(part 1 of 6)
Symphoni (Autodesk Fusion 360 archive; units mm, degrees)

design "Symphoni" references "Symphoni", "Back Panel", "Laser Panel", "Bearing_Test", "Cherry MX Keycap"
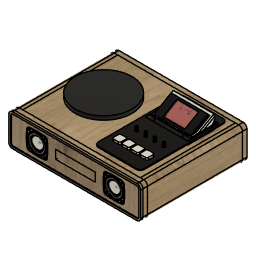
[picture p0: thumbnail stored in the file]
part number: Speaker 2 inch
parameter "Width" = 350
parameter "Height" = 85
parameter "Corner_Fillet" = 10
parameter "Length" = 216
parameter "M3_3D" = 3
parameter "M4_3D" = 4
parameter "M5_3D" = 5
parameter "Case_Holes" = 4 comment "The hole size of the screws holding the top plate to the sides"
sketch "Front_View" plane through (0, 0, 0) normal (0, 1, 0) x axis (1, 0, 0)
  line L1 (340, 0) -> (10, 0)
  line L2 (350, -75) -> (350, -10)
  line L3 (10, -85) -> (340, -85)
  line L4 (0, -10) -> (0, -75)
  line L5 (17, -78) -> (333, -78)
  line L6 (338, -70.8) -> (338, -17)
  line L7 (333, -12) -> (17, -12)
  line L8 (12, -17) -> (12, -71)
  line L9 (14.5, -73) -> (329.5, -73)
  line L10 (12, -14.5) -> (12, -70.5)
  line L11 (329.5, -12) -> (14.5, -12)
  line L12 (332, -70.5) -> (332, -14.5)
  line L13 (14, -73) -> (14.5, -73)
  line L14 (12, -12) -> (14.5, -12)
  line L15 (338, -12) -> (329.5, -12)
  line L16 (335.8, -73) -> (329.5, -73)
  line L17 (19.0012, -78) -> (19.0012, -85)
  line L18 (31.0012, -78) -> (19.0012, -78)
  line L19 (31.0012, -73) -> (31.0012, -78)
  line L20 (175, 0) -> (175, -85)
  line L21 (330.9988, -78) -> (330.9988, -85)
  line L22 (318.9988, -73) -> (318.9988, -78)
  arc A1 centre (10, -75) radius 10 clockwise from (10, -85) to (0, -75)
  arc A2 centre (340, -75) radius 10 clockwise from (350, -75) to (340, -85)
  arc A3 centre (340, -10) radius 10 clockwise from (340, 0) to (350, -10)
  arc A4 centre (10, -10) radius 10 clockwise from (0, -10) to (10, 0)
  arc A5 centre (17, -73) radius 5 clockwise from (17, -78) to (12, -73)
  arc A6 centre (17, -17) radius 5 clockwise from (12, -17) to (17, -12)
  arc A7 centre (333, -17) radius 5 clockwise from (333, -12) to (338, -17)
  arc A8 centre (333, -73) radius 5 clockwise from (338, -73) to (333, -78)
  arc A9 centre (14.5, -70.5) radius 2.5 clockwise from (14.5, -73) to (12, -70.5)
  arc A10 centre (329.5, -14.5) radius 2.5 clockwise from (329.5, -12) to (332, -14.5)
  arc A11 centre (329.5, -70.5) radius 2.5 clockwise from (332, -70.5) to (329.5, -73)
  arc A12 centre (14.5, -14.5) radius 2.5 clockwise from (12, -14.5) to (14.5, -12)
  arc A13 centre (14, -71) radius 2 clockwise from (14, -73) to (12, -71)
  arc A14 centre (335.8, -70.8) radius 2.2 clockwise from (338, -70.8) to (335.8, -73)
  point P1 (0, 0)
  point P2 (0, 0)
  point P4 (0, -85)
  point P3 (350, 0)
  point P41 (12, -12)
  point P42 (338, -12)
  point P43 (19.0012, -85)
  point P44 (19.0012, -78)
  point P45 (31.0012, -78)
  point P46 (31.0012, -73)
  point P47 (175, -85)
  point P48 (175, 0)
  point P49 (330.9988, -85)
  point P50 (330.9988, -78)
  point P51 (318.9988, -78)
  point P52 (318.9988, -73)
  point P18 (12, -73)
  point P27 (338, -73)
  horizontal L1
  vertical L2
  horizontal L3
  vertical L4
  coincident P1 P2
  coincident P4 L3
  coincident P4 L4
  tangent L3 A1
  tangent L4 A1
  tangent L2 A2
  tangent L3 A2
  equal A1 A2
  coincident P3 L1
  coincident P3 L2
  tangent L1 A3
  tangent L2 A3
  equal A1 A3
  coincident P2 L1
  coincident P2 L4
  tangent L1 A4
  tangent L4 A4
  equal A1 A4
  tangent L5 A5
  tangent L8 A5
  tangent L7 A6
  tangent L8 A6
  equal A5 A6
  tangent L6 A7
  tangent L7 A7
  equal A5 A7
  tangent L5 A8
  tangent L6 A8
  equal A5 A8
  tangent L9 A9
  tangent L10 A9
  tangent L11 A10
  tangent L12 A10
  equal A9 A10
  tangent L9 A11
  tangent L12 A11
  equal A9 A11
  tangent L10 A12
  tangent L11 A12
  equal A9 A12
  tangent A9 L13
  coincident L8 P41
  tangent A12 L14
  coincident L6 P42
  tangent A10 L15
  tangent A11 L16
  coincident L3 P43
  coincident L5 P44
  perpendicular L5 L17
  coincident L5 P45
  coincident L9 P46
  perpendicular L9 L19
  midpoint L3 P47
  midpoint L1 P48
  symmetric P43 L20 P49
  symmetric P44 L20 P50
  symmetric P45 L20 P51
  symmetric P46 L20 P52
  coincident L8 P18
  tangent L13 A13
  tangent L8 A13
  coincident L6 P27
  tangent L16 A14
  tangent L6 A14
  dimension "d3" distance P2 P3 = 350 (= "Width")
  dimension "d4" distance P2 P4 = 85 (= "Height")
  dimension "d5" radius A1 = 10 (= "Corner_Fillet")
  dimension "d8" radius A5 = 5 (= "Corner_Fillet / 2")
  dimension "d11" radius A9 = 2.5 (= "Corner_Fillet / 4")
  dimension "d12" distance P44 P45 = 12
  dimension "d13" radius A13 = 2
  dimension "d14" radius A14 = 2.2
extrude "Extrude1" new body sketch "Front_View" profile of L1 L2 L3 L4 A1 A2 A3 A4 L5 L7 L6 L8 A6 A7 L9 L11 L10 A12 L13 L15 L16 L17 L18 L19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 along normal blind 216 (= "Length")
sketch "Case_Hole" plane through (0, 0, 78) normal (0, 0, 1) x axis (-1, 0, 0)
  line L1 (-31.0012, 0) -> (-19.0012, 0)
  line L2 (-31.0012, -216) -> (-31.0012, 0)
  line L3 (-19.0012, -216) -> (-31.0012, -216)
  line L4 (-19.0012, 0) -> (-19.0012, -216)
  line L5 (-330.9988, 0) -> (-318.9988, 0)
  line L6 (-330.9988, -216) -> (-330.9988, 0)
  line L7 (-318.9988, -216) -> (-330.9988, -216)
  line L8 (-318.9988, 0) -> (-318.9988, -216)
  line L9 (-19.0012, -198) -> (-330.9988, -198)
  line L10 (-18.9896, -180) -> (-331.0104, -180)
  line L11 (-19.0012, -162) -> (-330.9988, -162)
  line L12 (-19.0012, -144) -> (-330.9988, -144)
  line L13 (-20, -126) -> (-330.9988, -126)
  line L14 (-333, -216) -> (-17, -216)
  line L15 (0, -18) -> (-330.9988, -18)
  line L16 (0.0025, -36) -> (-330.9988, -36)
  line L17 (0, -54) -> (-330.9988, -54)
  line L18 (-333, 0) -> (-17, 0)
  line L19 (-324.9988, -216) -> (-324.9988, 0)
  line L20 (-25.0012, -216) -> (-25.0012, 0)
  line L21 (-175, -216) -> (-175, 0)
  line L22 (-340, -108) -> (-19.0012, -108)
  circle C1 centre (-324.9988, -189) radius 2
  circle C2 centre (-324.9988, -27) radius 3.4926
  circle C3 centre (-25.0012, -188.5138) radius 2.9725
  circle C4 centre (-25.0012, -27.4042) radius 3.2246
  circle C5 centre (-25.0012, -189) radius 2
  circle C6 centre (-324.9988, -108) radius 2
  circle C7 centre (-25.0012, -108) radius 2
  point P10 (-330.9988, -198)
  point P11 (-19.0012, -198)
  point P14 (-330.9988, -162)
  point P15 (-19.0012, -162)
  point P16 (-330.9988, -144)
  point P17 (-19.0012, -144)
  point P18 (-330.9988, -126)
  point P22 (-330.9988, -18)
  point P24 (-330.9988, -36)
  point P26 (-330.9988, -54)
  point P30 (-324.9988, 0)
  point P31 (-324.9988, -216)
  point P32 (-25.0012, 0)
  point P33 (-25.0012, -216)
  point P34 (-324.9988, -189)
  point P35 (-324.9988, -27)
  point P36 (-25.0012, -188.5138)
  point P37 (-25.0012, -27.4042)
  point P38 (-175, 0)
  point P39 (-175, -216)
  point P40 (-25.0012, -27)
  point P42 (-19.0012, -108)
  point P44 (-324.9988, -108)
  coincident L6 P10
  coincident L4 P11
  perpendicular L4 L9
  coincident L6 P14
  coincident L4 P15
  perpendicular L4 L11
  coincident L6 P16
  coincident L4 P17
  perpendicular L4 L12
  coincident L6 P18
  perpendicular L2 L13
  horizontal L10
  coincident L6 P22
  perpendicular L6 L15
  coincident L6 P24
  coincident L6 P26
  perpendicular L2 L17
  horizontal L16
  midpoint L5 P30
  midpoint L7 P31
  midpoint L1 P32
  midpoint L3 P33
  coincident L19 P34
  coincident L19 P35
  coincident L20 P36
  coincident L20 P37
  midpoint L18 P38
  midpoint L14 P39
  symmetric C1 L21 C5
  symmetric P35 L21 P40
  midpoint L4 P42
  perpendicular L6 L22
  midpoint L19 P44
  symmetric L21 C6 C7
  dimension "d21" distance L9 L14 = 18
  dimension "d22" distance L9 L10 = 18
  dimension "d23" distance L15 L18 = 18
  dimension "d24" distance L15 L16 = 18
  dimension "d25" distance L16 L17 = 18
  dimension "d26" distance L10 L11 = 18
  dimension "d27" distance L11 L12 = 18
  dimension "d28" distance L12 L13 = 18
  dimension "d29" diameter C1 = 4 (= "Case_Holes")
  dimension "d30" distance L9 P34 = 9 (= "d22 / 2")
  dimension "d31" distance L15 P35 = 9 (= "d24 / 2")
  dimension "d34" diameter C6 = 4 (= "Case_Holes")
extrude "Extrude2" cut sketch "Case_Hole" profile of L17 C1 C2 C3 C4 C5 C6 C7 to an object
extrude "Extrude1" new body sketch "Front_View" profile of L3 L5 L9 L17 L18 L19 L21 L22 along normal blind 216 (= "Length")
extrude "Extrude2" cut sketch "Case_Hole" profile of L17 C1 C2 C3 C4 C5 C6 C7 along normal blind 4
sketch "Sketch3" plane through (0, 0, 85) normal (0, 0, 1) x axis (-1, 0, 0)
  line L1 (-330.9988, 0) -> (-19.0012, 0)
  line L2 (-330.9988, -216) -> (-330.9988, 0)
  line L3 (-19.0012, -216) -> (-330.9988, -216)
  line L4 (-19.0012, 0) -> (-19.0012, -216)
  line L5 (-315.3243, -196.9924) -> (-215.3243, -196.9924)
  line L6 (-315.3243, -25.6421) -> (-315.3243, -196.9924)
  line L7 (-215.3243, -25.6421) -> (-315.3243, -25.6421)
  line L8 (-215.3243, -196.9924) -> (-215.3243, -25.6421)
  circle C1 centre (-110, -108) radius 88.9
  point P6 (-110, -108)
  point P7 (-215.3243, -196.9924)
  point P8 (-315.3243, -196.9924)
  horizontal L5
  vertical L6
  horizontal L7
  vertical L8
  dimension "d40" diameter C1 = 177.8
  dimension "d41" distance L3 P6 = 108 (= "Length / 2")
  dimension "d42" distance P7 P8 = 100
sketch "Sketch1" plane through (0, 216, 0) normal (0, 1, 0) x axis (-1, 0, 0)
  line L1 (-330.9988, 78) -> (-330.9988, 85)
  line L2 (-318.9988, 78) -> (-330.9988, 78)
  line L3 (-318.9988, 73) -> (-318.9988, 78)
  line L4 (-31.0012, 73) -> (-318.9988, 73)
  line L5 (-31.0012, 78) -> (-31.0012, 73)
  line L6 (-19.0012, 78) -> (-31.0012, 78)
  line L7 (-19.0012, 85) -> (-19.0012, 78)
  line L8 (-330.9988, 85) -> (-19.0012, 85)
  line L9 (-318.9988, 73) -> (-335.8, 73)
  line L10 (-318.9988, 78) -> (-318.9988, 73)
  line L11 (-330.9988, 78) -> (-318.9988, 78)
  line L12 (-330.9988, 85) -> (-330.9988, 78)
  line L13 (-340, 85) -> (-330.9988, 85)
  line L14 (-350, 10) -> (-350, 75)
  line L15 (-10, 0) -> (-340, 0)
  line L16 (0, 75) -> (0, 10)
  line L17 (-19.0012, 85) -> (-10, 85)
  line L18 (-19.0012, 78) -> (-19.0012, 85)
  line L19 (-31.0012, 78) -> (-19.0012, 78)
  line L20 (-31.0012, 73) -> (-31.0012, 78)
  line L21 (-14, 73) -> (-31.0012, 73)
  line L22 (-12, 17) -> (-12, 71)
  line L23 (-333, 12) -> (-17, 12)
  line L24 (-338, 70.8) -> (-338, 17)
  line L25 (-175, 0) -> (-175, 85)
  line L26 (-350, 42.5) -> (0, 42.5)
  line L27 (-217.5, 25) -> (-132.5, 25)
  line L28 (-222.5, 55) -> (-222.5, 30)
  line L29 (-132.5, 60) -> (-217.5, 60)
  line L30 (-127.5, 30) -> (-127.5, 55)
  line L31 (-222.5, 60) -> (-127.5, 25)
  line L32 (-127.5, 60) -> (-222.5, 25)
  arc A1 centre (-340, 75) radius 10 clockwise from (-350, 75) to (-340, 85)
  arc A2 centre (-340, 10) radius 10 clockwise from (-340, 0) to (-350, 10)
  arc A3 centre (-10, 10) radius 10 clockwise from (0, 10) to (-10, 0)
  arc A4 centre (-10, 75) radius 10 clockwise from (-10, 85) to (0, 75)
  arc A5 centre (-14, 71) radius 2 clockwise from (-14, 73) to (-12, 71)
  arc A6 centre (-17, 17) radius 5 clockwise from (-12, 17) to (-17, 12)
  arc A7 centre (-333, 17) radius 5 clockwise from (-333, 12) to (-338, 17)
  arc A8 centre (-335.8, 70.8) radius 2.2 clockwise from (-338, 70.8) to (-335.8, 73)
  arc A9 centre (-217.5, 55) radius 5 clockwise from (-222.5, 55) to (-217.5, 60)
  arc A10 centre (-132.5, 55) radius 5 clockwise from (-132.5, 60) to (-127.5, 55)
  arc A11 centre (-132.5, 30) radius 5 clockwise from (-127.5, 30) to (-132.5, 25)
  arc A12 centre (-217.5, 30) radius 5 clockwise from (-217.5, 25) to (-222.5, 30)
  point P42 (-175, 85)
  point P43 (-175, 0)
  point P44 (0, 42.5)
  point P45 (-350, 42.5)
  point P50 (-175, 42.5)
  point P48 (-222.5, 60)
  point P49 (-127.5, 60)
  point P46 (-127.5, 25)
  point P47 (-222.5, 25)
  midpoint L8 P42
  midpoint L15 P43
  midpoint L16 P44
  midpoint L14 P45
  horizontal L27
  perpendicular L27 L28
  parallel L27 L29
  parallel L28 L30
  coincident L31 P50
  coincident L32 P50
  midpoint L25 P50
  coincident P48 L29
  coincident P48 L28
  tangent L29 A9
  tangent L28 A9
  coincident P49 L29
  coincident P49 L30
  tangent L29 A10
  tangent L30 A10
  equal A9 A10
  coincident P46 L27
  coincident P46 L30
  tangent L27 A11
  tangent L30 A11
  equal A9 A11
  coincident P47 L28
  coincident P47 L27
  tangent L28 A12
  tangent L27 A12
  equal A9 A12
  dimension "d45" distance P48 P49 = 95
  dimension "d46" distance P47 P48 = 35
  dimension "d47" radius A9 = 5
extrude "Extrude1" new body sketch "Sketch1" profile of L1 L2 L3 L4 L5 L6 L7 L8 L9 L10 L11 L12 L13 A1 L14 A2 L15 A3 L16 A4 L17 L18 L19 L20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 along normal blind 12
extrude "Extrude3" cut sketch "Sketch3" profile of L5 L6 L7 L8 against normal blind 25
component_insert "Component Insert2"
component_from_bodies "Body->Comp1"
sketch "Sketch2" plane through (0, 216, 0) normal (0, 1, 0) x axis (-1, 0, 0)
  line L1 (-318.9988, 73) -> (-335.8, 73)
  line L2 (-318.9988, 78) -> (-318.9988, 73)
  line L3 (-330.9988, 78) -> (-318.9988, 78)
  line L4 (-330.9988, 85) -> (-330.9988, 78)
  line L5 (-340, 85) -> (-330.9988, 85)
  line L6 (-350, 10) -> (-350, 75)
  line L7 (-10, 0) -> (-340, 0)
  line L8 (0, 75) -> (0, 10)
  line L9 (-19.0012, 85) -> (-10, 85)
  line L10 (-19.0012, 78) -> (-19.0012, 85)
  line L11 (-31.0012, 78) -> (-19.0012, 78)
  line L12 (-31.0012, 73) -> (-31.0012, 78)
  line L13 (-14, 73) -> (-31.0012, 73)
  line L14 (-12, 17) -> (-12, 71)
  line L15 (-333, 12) -> (-17, 12)
  line L16 (-338, 70.8) -> (-338, 17)
  arc A1 centre (-340, 75) radius 10 clockwise from (-350, 75) to (-340, 85)
  arc A2 centre (-340, 10) radius 10 clockwise from (-340, 0) to (-350, 10)
  arc A3 centre (-10, 10) radius 10 clockwise from (0, 10) to (-10, 0)
  arc A4 centre (-10, 75) radius 10 clockwise from (-10, 85) to (0, 75)
  arc A5 centre (-14, 71) radius 2 clockwise from (-14, 73) to (-12, 71)
  arc A6 centre (-17, 17) radius 5 clockwise from (-12, 17) to (-17, 12)
  arc A7 centre (-333, 17) radius 5 clockwise from (-333, 12) to (-338, 17)
  arc A8 centre (-335.8, 70.8) radius 2.2 clockwise from (-338, 70.8) to (-335.8, 73)
  circle C1 centre (-340, 78) radius 2
  circle C2 centre (-340, 6.9916) radius 2
  circle C3 centre (-175, 6.9916) radius 2
  circle C4 centre (-175, 79) radius 2
  circle C5 centre (-9.989, 78) radius 2
  circle C6 centre (-10, 7.35) radius 2
  dimension "d52" diameter C1 = 4 (= "Case_Holes")
  dimension "d53" diameter C2 = 4 (= "Case_Holes")
  dimension "d54" diameter C3 = 4 (= "Case_Holes")
  dimension "d55" diameter C4 = 4 (= "Case_Holes")
  dimension "d56" diameter C5 = 4 (= "Case_Holes")
  dimension "d57" diameter C6 = 4 (= "Case_Holes")
extrude "Extrude4" cut sketch "Sketch2" profile of C1 C2 C3 C4 C5 C6 against normal blind 5 and along normal blind 15
sketch "Sketch3" plane through (0, 0, 85) normal (0, 0, 1) x axis (-1, 0, 0)
  line L1 (-315.3243, -25.6421) -> (-315.3243, -196.9924)
  line L2 (-215.3243, -25.6421) -> (-315.3243, -25.6421)
  line L3 (-215.3243, -196.9924) -> (-215.3243, -25.6421)
  line L4 (-315.3243, -196.9924) -> (-215.3243, -196.9924)
  line L5 (-330.9988, 0) -> (-19.0012, 0)
  line L6 (-330.9988, -216) -> (-330.9988, 0)
  line L7 (-19.0012, -216) -> (-330.9988, -216)
  line L8 (-19.0012, 0) -> (-19.0012, -216)
  line L9 (-214.0809, -145.3115) -> (-311.7625, -145.3115)
  line L10 (-214.0809, -198.1908) -> (-214.0809, -145.3115)
  line L11 (-311.7625, -198.1908) -> (-214.0809, -198.1908)
  line L12 (-311.7625, -145.3115) -> (-311.7625, -198.1908)
  line L13 (-316.7625, -140.3115) -> (-209.0809, -140.3115)
  line L14 (-316.7625, -203.1908) -> (-316.7625, -140.3115)
  line L15 (-209.0809, -203.1908) -> (-316.7625, -203.1908)
  line L16 (-209.0809, -140.3115) -> (-209.0809, -203.1908)
  line L17 (-318.7625, -138.3115) -> (-207.0809, -138.3115)
  line L18 (-318.7625, -205.1908) -> (-318.7625, -138.3115)
  line L19 (-207.0809, -205.1908) -> (-318.7625, -205.1908)
  line L20 (-207.0809, -138.3115) -> (-207.0809, -205.1908)
  dimension "d75" = 2
extrude "Extrude6" cut sketch "Sketch3" profile of L1 L3 L4 L9 L10 L11 L12 L13 L14 L15 L16 L18 L17 L19 L20 against normal blind 20
sketch "Sketch11" plane through (0, 227.5, 0) normal (0, -1, 0) x axis (1, 0, 0)
  line L1 (227.4494, 58.544) -> (227.4494, 28.544)
  line L2 (127.4494, 63.544) -> (222.4494, 63.544)
  line L3 (122.4494, 28.544) -> (122.4494, 58.544)
  line L4 (222.4494, 23.544) -> (127.4494, 23.544)
  line L5 (193.2946, 52.6567) -> (193.2946, 61.6567)
  line L6 (186.2946, 52.6567) -> (193.2946, 52.6567)
  line L7 (186.2946, 61.6567) -> (186.2946, 52.6567)
  line L8 (193.2946, 61.6567) -> (186.2946, 61.6567)
  line L9 (186.291, 51.1467) -> (186.291, 46.6467)
  line L10 (193.291, 51.1467) -> (186.291, 51.1467)
  line L11 (193.291, 46.6467) -> (193.291, 51.1467)
  line L12 (186.291, 46.6467) -> (193.291, 46.6467)
  line L13 (137.5637, 51.1467) -> (137.5637, 45.1467)
  line L14 (144, 51.1467) -> (137.5637, 51.1467)
  line L15 (144, 45.1467) -> (144, 51.1467)
  line L16 (137.5637, 45.1467) -> (144, 45.1467)
  line L17 (159.4932, 39.0374) -> (159.4932, 49.0374)
  line L18 (152.4932, 39.0374) -> (159.4932, 39.0374)
  line L19 (152.4932, 49.0374) -> (152.4932, 39.0374)
  line L20 (159.4932, 49.0374) -> (152.4932, 49.0374)
  line L21 (194.5687, 39.0374) -> (194.5687, 45.5374)
  line L22 (187.5687, 39.0374) -> (194.5687, 39.0374)
  line L23 (187.5687, 45.5374) -> (187.5687, 39.0374)
  line L24 (194.5687, 45.5374) -> (187.5687, 45.5374)
  line L25 (170.35, 37.6424) -> (170.35, 27.0424)
  line L26 (179.65, 37.6424) -> (170.35, 37.6424)
  line L27 (179.65, 27.0424) -> (179.65, 37.6424)
  line L28 (171.05, 26.3424) -> (178.95, 26.3424)
  line L29 (127.5, 30) -> (127.5, 55)
  line L30 (132.5, 60) -> (217.5, 60)
  line L31 (217.5, 25) -> (132.5, 25)
  line L32 (222.5, 55) -> (222.5, 30)
  line L33 (129.5, 30) -> (129.5, 55)
  line L34 (217.5, 27) -> (132.5, 27)
  line L35 (220.5, 55) -> (220.5, 30)
  line L36 (132.5, 58) -> (217.5, 58)
  line L37 (182, 27) -> (167, 27)
  line L38 (182, 25) -> (182, 27)
  line L39 (167, 25) -> (182, 25)
  line L40 (167, 27) -> (167, 25)
  arc A1 centre (222.4494, 28.544) radius 5 clockwise from (227.4494, 28.544) to (222.4494, 23.544)
  arc A2 centre (222.4494, 58.544) radius 5 clockwise from (222.4494, 63.544) to (227.4494, 58.544)
  arc A3 centre (127.4494, 58.544) radius 5 clockwise from (122.4494, 58.544) to (127.4494, 63.544)
  arc A4 centre (127.4494, 28.544) radius 5 clockwise from (127.4494, 23.544) to (122.4494, 28.544)
  circle C1 centre (175, 46.2153) radius 2.7
  arc A5 centre (178.95, 27.0424) radius 0.7 clockwise from (179.65, 27.0424) to (178.95, 26.3424)
  arc A6 centre (171.05, 27.0424) radius 0.7 clockwise from (171.05, 26.3424) to (170.35, 27.0424)
  arc A7 centre (132.5, 55) radius 5 clockwise from (127.5, 55) to (132.5, 60)
  arc A8 centre (132.5, 30) radius 5 clockwise from (132.5, 25) to (127.5, 30)
  arc A9 centre (217.5, 30) radius 5 clockwise from (222.5, 30) to (217.5, 25)
  arc A10 centre (217.5, 55) radius 5 clockwise from (217.5, 60) to (222.5, 55)
  arc A11 centre (132.5, 30) radius 3 clockwise from (132.5, 27) to (129.5, 30)
  arc A12 centre (217.5, 30) radius 3 clockwise from (220.5, 30) to (217.5, 27)
  arc A13 centre (217.5, 55) radius 3 clockwise from (217.5, 58) to (220.5, 55)
  arc A14 centre (132.5, 55) radius 3 clockwise from (129.5, 55) to (132.5, 58)
  point P69 (182, 25)
  point P67 (167, 27)
  horizontal L37
  vertical L38
  horizontal L39
  vertical L40
  coincident L31 P69
  coincident L34 P67
  dimension "d141" = -2
offset_faces "OffsetFaces1" distance 36
position "Position9"
sketch "Sketch12" plane through (0, 0, 88.7) normal (0, 0, 1) x axis (-1, 0, 0)
  line L1 (-313.7625, -161.3779) -> (-313.7625, -215.1735)
  line L2 (-206.1516, -161.3779) -> (-313.7625, -161.3779)
  line L3 (-206.1516, -186.4735) -> (-206.1516, -161.3779)
  line L4 (-206.1515, -186.4735) -> (-206.1516, -186.4735)
  line L5 (-206.1515, -188.1735) -> (-206.1515, -186.4735)
  line L6 (-206.1516, -188.1735) -> (-206.1515, -188.1735)
  line L7 (-206.1516, -213.4735) -> (-206.1516, -188.1735)
  line L8 (-206.1515, -213.4735) -> (-206.1516, -213.4735)
  line L9 (-206.1515, -215.1735) -> (-206.1515, -213.4735)
  line L10 (-313.7625, -215.1735) -> (-206.1515, -215.1735)
  line L11 (-313.7625, -125.5942) -> (-313.7625, -152.5942)
  line L12 (-206.1516, -125.5942) -> (-313.7625, -125.5942)
  line L13 (-206.1516, -152.5942) -> (-206.1516, -125.5942)
  line L14 (-313.7625, -152.5942) -> (-206.1516, -152.5942)
  line L15 (-209.081, -225) -> (-311.081, -225)
  line L16 (-199.081, -5) -> (-199.081, -215)
  line L17 (-311.081, 5) -> (-209.081, 5)
  line L18 (-321.081, -215) -> (-321.081, -5)
  arc A1 centre (-311.081, -215) radius 10 clockwise from (-311.081, -225) to (-321.081, -215)
  arc A2 centre (-209.081, -215) radius 10 clockwise from (-199.081, -215) to (-209.081, -225)
  arc A3 centre (-209.081, -5) radius 10 clockwise from (-209.081, 5) to (-199.081, -5)
  arc A4 centre (-311.081, -5) radius 10 clockwise from (-321.081, -5) to (-311.081, 5)
sketch "Sketch13" plane through (0, 0, 0) normal (0, -1, 0) x axis (1, 0, 0)
  line L1 (330.9988, 85) -> (330.9988, 78)
  line L2 (19.0012, 85) -> (330.9988, 85)
  line L3 (19.0012, 78) -> (19.0012, 85)
  line L4 (31.0012, 78) -> (19.0012, 78)
  line L5 (31.0012, 73) -> (31.0012, 78)
  line L6 (318.9988, 73) -> (31.0012, 73)
  line L7 (318.9988, 78) -> (318.9988, 73)
  line L8 (330.9988, 78) -> (318.9988, 78)
  line L9 (335.8, 73) -> (318.9988, 73)
  line L10 (338, 17) -> (338, 70.8)
  line L11 (17, 12) -> (333, 12)
  line L12 (12, 71) -> (12, 17)
  line L13 (31.0012, 73) -> (14, 73)
  line L14 (31.0012, 78) -> (31.0012, 73)
  line L15 (19.0012, 78) -> (31.0012, 78)
  line L16 (19.0012, 85) -> (19.0012, 78)
  line L17 (10, 85) -> (19.0012, 85)
  line L18 (0, 10) -> (0, 75)
  line L19 (340, 0) -> (10, 0)
  line L20 (350, 75) -> (350, 10)
  line L21 (330.9988, 85) -> (340, 85)
  line L22 (330.9988, 78) -> (330.9988, 85)
  line L23 (318.9988, 78) -> (330.9988, 78)
  line L24 (318.9988, 73) -> (318.9988, 78)
  arc A1 centre (335.8, 70.8) radius 2.2 clockwise from (335.8, 73) to (338, 70.8)
  arc A2 centre (333, 17) radius 5 clockwise from (338, 17) to (333, 12)
  arc A3 centre (17, 17) radius 5 clockwise from (17, 12) to (12, 17)
  arc A4 centre (14, 71) radius 2 clockwise from (12, 71) to (14, 73)
  arc A5 centre (10, 75) radius 10 clockwise from (0, 75) to (10, 85)
  arc A6 centre (10, 10) radius 10 clockwise from (10, 0) to (0, 10)
  arc A7 centre (340, 10) radius 10 clockwise from (350, 10) to (340, 0)
  arc A8 centre (340, 75) radius 10 clockwise from (340, 85) to (350, 75)
place_component sketch "Sketch13"
extrude "Extrude1" new body sketch "Sketch13" along normal blind 12
component_insert "Component Insert7"
position "Position10"
sketch "Sketch14" plane through (0, 0, 0) normal (0, -1, 0) x axis (1, 0, 0)
  line L1 (335.8, 73) -> (318.9988, 73)
  line L2 (338, 17) -> (338, 70.8)
  line L3 (17, 12) -> (333, 12)
  line L4 (12, 71) -> (12, 17)
  line L5 (31.0012, 73) -> (14, 73)
  line L6 (31.0012, 78) -> (31.0012, 73)
  line L7 (19.0012, 78) -> (31.0012, 78)
  line L8 (19.0012, 85) -> (19.0012, 78)
  line L9 (10, 85) -> (19.0012, 85)
  line L10 (0, 10) -> (0, 75)
  line L11 (340, 0) -> (10, 0)
  line L12 (350, 75) -> (350, 10)
  line L13 (330.9988, 85) -> (340, 85)
  line L14 (330.9988, 78) -> (330.9988, 85)
  line L15 (318.9988, 78) -> (330.9988, 78)
  line L16 (318.9988, 73) -> (318.9988, 78)
  line L17 (330.9988, 85) -> (19.0012, 85)
  line L18 (31.0012, 73) -> (318.9988, 73)
  arc A1 centre (335.8, 70.8) radius 2.2 clockwise from (335.8, 73) to (338, 70.8)
  arc A2 centre (333, 17) radius 5 clockwise from (338, 17) to (333, 12)
  arc A3 centre (17, 17) radius 5 clockwise from (17, 12) to (12, 17)
  arc A4 centre (14, 71) radius 2 clockwise from (12, 71) to (14, 73)
  arc A5 centre (10, 75) radius 10 clockwise from (0, 75) to (10, 85)
  arc A6 centre (10, 10) radius 10 clockwise from (10, 0) to (0, 10)
  arc A7 centre (340, 10) radius 10 clockwise from (350, 10) to (340, 0)
  arc A8 centre (340, 75) radius 10 clockwise from (340, 85) to (350, 75)
  point P18 (19.0012, 85)
  point P34 (19.0012, 85)
  point P31 (330.9988, 85)
  point P35 (330.9988, 85)
  point P2 (318.9988, 73)
  point P36 (318.9988, 73)
  point P15 (31.0012, 73)
  point P37 (31.0012, 73)
  coincident P18 P34
  coincident P31 P35
  coincident P2 P36
  coincident P15 P37
extrude "Extrude6" new body sketch "Sketch14" along normal blind 18 bodies "Front"
sketch "Sketch15" plane through (0, -18, 0) normal (0, -1, 0) x axis (1, 0, 0)
  line L1 (0, 10) -> (0, 75)
  line L2 (340, 0) -> (10, 0)
  line L3 (350, 75) -> (350, 10)
  line L4 (10, 85) -> (340, 85)
  line L5 (10, 80) -> (340, 80)
  line L6 (5, 10) -> (5, 75)
  line L7 (340, 5) -> (10, 5)
  line L8 (345, 75) -> (345, 10)
  arc A1 centre (10, 75) radius 10 clockwise from (0, 75) to (10, 85)
  arc A2 centre (10, 10) radius 10 clockwise from (10, 0) to (0, 10)
  arc A3 centre (340, 10) radius 10 clockwise from (350, 10) to (340, 0)
  arc A4 centre (340, 75) radius 10 clockwise from (340, 85) to (350, 75)
  arc A5 centre (10, 75) radius 5 clockwise from (5, 75) to (10, 80)
  arc A6 centre (10, 10) radius 5 clockwise from (10, 5) to (5, 10)
  arc A7 centre (340, 10) radius 5 clockwise from (345, 10) to (340, 5)
  arc A8 centre (340, 75) radius 5 clockwise from (340, 80) to (345, 75)
  dimension "d148" = -5
extrude "Extrude7" cut sketch "Sketch15" profile of A8 L6 A6 L8 L5 L7 A5 A7 against normal blind 2
base_feature "Base Feature1"
position "Position11"
sketch "Sketch16" plane through (0, -16, 0) normal (0, -1, 0) x axis (1, 0, 0)
  line L1 (10, 80) -> (340, 80)
  line L2 (5, 10) -> (5, 75)
  line L3 (340, 5) -> (10, 5)
  line L4 (345, 75) -> (345, 10)
  line L5 (175, 0) -> (175, 85)
  line L6 (5, 42.5) -> (345, 42.5)
  line L7 (44.9825, 14.5) -> (100.9825, 14.5)
  line L8 (44.9825, 70.5) -> (44.9825, 14.5)
  line L9 (100.9825, 70.5) -> (44.9825, 70.5)
  line L10 (100.9825, 14.5) -> (100.9825, 70.5)
  line L11 (44.9825, 70.5) -> (100.9825, 14.5)
  line L12 (100.9825, 70.5) -> (44.9825, 14.5)
  arc A1 centre (340, 75) radius 5 clockwise from (340, 80) to (345, 75)
  arc A2 centre (10, 75) radius 5 clockwise from (5, 75) to (10, 80)
  arc A3 centre (10, 10) radius 5 clockwise from (10, 5) to (5, 10)
  arc A4 centre (340, 10) radius 5 clockwise from (345, 10) to (340, 5)
  circle C1 centre (277.0175, 42.5) radius 27.5
  point P16 (345, 42.5)
  point P17 (5, 42.5)
  point P18 (277.0175, 42.5)
  point P23 (72.9825, 42.5)
  point P21 (44.9825, 70.5)
  point P22 (100.9825, 70.5)
  point P20 (44.9825, 14.5)
  perpendicular L1 L5
  midpoint L4 P16
  midpoint L2 P17
  coincident L6 P18
  horizontal L7
  perpendicular L7 L8
  parallel L7 L9
  parallel L8 L10
  coincident L11 P23
  coincident L12 P23
  dimension "d152" diameter C1 = 55
  dimension "d153" distance P21 P22 = 56
  dimension "d154" distance P20 P21 = 56
joint "Assemble3" GlobalReorient0 0 GlobalReorient1 0 alignAngle 90 alignOffsetX 0 alignOffsetY 0 alignOffsetZ -4 GlobalReorient0 0 GlobalReorient1 0 GlobalReorient0 0 GlobalReorient1 0 GlobalReorient0 0 GlobalReorient1 0 GlobalReorient0 0 GlobalReorient1 0 GlobalReorient0 0 GlobalReorient1 0 GlobalReorient0 0 GlobalReorient1 0 GlobalReorient0 0 GlobalReorient1 0
sketch "Sketch17" plane through (145.965, -16.0943, 85) normal (0, -1, 0) x axis (-1, 0, 0)
  line L1 (54.11, 64.2009) -> (53.4029, 64.908)
  line L2 (50.5745, 62.0796) -> (51.2816, 61.3725)
  line L3 (51.2816, 23.6275) -> (50.5745, 22.9204)
  line L4 (53.4029, 20.092) -> (54.11, 20.7991)
  line L5 (91.855, 20.7991) -> (92.5621, 20.092)
  line L6 (95.3905, 22.9204) -> (94.6834, 23.6275)
  line L7 (94.6834, 61.3725) -> (95.3905, 62.0796)
  line L8 (92.5621, 64.908) -> (91.855, 64.2009)
  line L9 (135.965, 5) -> (-194.035, 5)
  line L10 (140.965, 75) -> (140.965, 10)
  line L11 (-194.035, 80) -> (135.965, 80)
  line L12 (-199.035, 10) -> (-199.035, 75)
  line L13 (140.965, 42.5) -> (-199.035, 42.5)
  line L14 (-29.035, 80) -> (-29.035, 5)
  line L15 (23.5429, 53.9909) -> (-81.6129, 53.9909)
  line L16 (23.5429, 31.0091) -> (23.5429, 53.9909)
  line L17 (-81.6129, 31.0091) -> (23.5429, 31.0091)
  line L18 (-81.6129, 53.9909) -> (-81.6129, 31.0091)
  line L19 (23.5429, 31.0091) -> (-81.6129, 53.9909)
  line L20 (-81.6129, 31.0091) -> (23.5429, 53.9909)
  line L21 (-72.6746, 31.0091) -> (-81.6129, 31.0091)
  line L22 (-72.6746, 53.9909) -> (-72.6746, 31.0091)
  line L23 (-81.6129, 53.9909) -> (-72.6746, 53.9909)
  line L24 (-81.6129, 31.0091) -> (-81.6129, 53.9909)
  arc A1 centre (51.9887, 21.5062) radius 4 clockwise from (51.4177, 17.5472) to (48.0296, 20.9352)
  arc A2 centre (72.9825, 167.0625) radius 151.0625 clockwise from (94.5473, 17.5472) to (51.4177, 17.5472)
  arc A3 centre (93.9763, 21.5062) radius 4 clockwise from (97.9353, 20.9352) to (94.5473, 17.5472)
  arc A4 centre (-51.58, 42.5) radius 151.0625 clockwise from (97.9353, 64.0648) to (97.9353, 20.9352)
  arc A5 centre (93.9763, 63.4938) radius 4 clockwise from (94.5473, 67.4528) to (97.9353, 64.0648)
  arc A6 centre (72.9825, -82.0625) radius 151.0625 clockwise from (51.4177, 67.4528) to (94.5473, 67.4528)
  arc A7 centre (51.9887, 63.4938) radius 4 clockwise from (48.0296, 64.0648) to (51.4177, 67.4528)
  arc A8 centre (197.545, 42.5) radius 151.0625 clockwise from (48.0296, 20.9352) to (48.0296, 64.0648)
  circle C1 centre (72.9825, 42.5) radius 25.7849
  arc A9 centre (51.9887, 63.4938) radius 2 clockwise from (50.5745, 62.0796) to (53.4029, 64.908)
  arc A10 centre (52.6958, 62.7867) radius 2 clockwise from (54.11, 64.2009) to (51.2816, 61.3725)
  arc A11 centre (51.9887, 21.5062) radius 2 clockwise from (53.4029, 20.092) to (50.5745, 22.9204)
  arc A12 centre (52.6958, 22.2133) radius 2 clockwise from (51.2816, 23.6275) to (54.11, 20.7991)
  arc A13 centre (93.9763, 21.5062) radius 2 clockwise from (95.3905, 22.9204) to (92.5621, 20.092)
  arc A14 centre (93.2692, 22.2133) radius 2 clockwise from (91.855, 20.7991) to (94.6834, 23.6275)
  arc A15 centre (93.9763, 63.4938) radius 2 clockwise from (92.5621, 64.908) to (95.3905, 62.0796)
  arc A16 centre (93.2692, 62.7867) radius 2 clockwise from (94.6834, 61.3725) to (91.855, 64.2009)
  arc A17 centre (197.545, 42.5) radius 151.0625 clockwise from (48.0296, 20.9352) to (48.0296, 64.0648)
  circle C2 centre (72.9825, 42.5) radius 25.7849
  arc A18 centre (72.9825, -82.0625) radius 151.0625 clockwise from (51.4177, 67.4528) to (94.5473, 67.4528)
  arc A19 centre (51.9887, 63.4938) radius 4 clockwise from (48.0296, 64.0648) to (51.4177, 67.4528)
  arc A20 centre (197.545, 42.5) radius 151.0625 clockwise from (48.0296, 20.9352) to (48.0296, 64.0648)
  arc A21 centre (51.9887, 21.5062) radius 4 clockwise from (51.4177, 17.5472) to (48.0296, 20.9352)
  arc A22 centre (72.9825, 167.0625) radius 151.0625 clockwise from (94.5473, 17.5472) to (51.4177, 17.5472)
  arc A23 centre (93.9763, 21.5062) radius 4 clockwise from (97.9353, 20.9352) to (94.5473, 17.5472)
  arc A24 centre (-51.58, 42.5) radius 151.0625 clockwise from (97.9353, 64.0648) to (97.9353, 20.9352)
  arc A25 centre (93.9763, 63.4938) radius 4 clockwise from (94.5473, 67.4528) to (97.9353, 64.0648)
  arc A26 centre (197.545, 42.5) radius 153.0625 clockwise from (46.0501, 20.6497) to (46.0501, 64.3503)
  arc A27 centre (51.9887, 21.5062) radius 6 clockwise from (51.1322, 15.5676) to (46.0501, 20.6497)
  arc A28 centre (72.9825, 167.0625) radius 153.0625 clockwise from (94.8328, 15.5676) to (51.1322, 15.5676)
  arc A29 centre (93.9763, 21.5062) radius 6 clockwise from (99.9148, 20.6497) to (94.8328, 15.5676)
  arc A30 centre (-51.58, 42.5) radius 153.0625 clockwise from (99.9148, 64.3503) to (99.9148, 20.6497)
  arc A31 centre (93.9763, 63.4938) radius 6 clockwise from (94.8328, 69.4324) to (99.9148, 64.3503)
  arc A32 centre (72.9825, -82.0625) radius 153.0625 clockwise from (51.1322, 69.4324) to (94.8328, 69.4324)
  arc A33 centre (51.9887, 63.4938) radius 6 clockwise from (46.0501, 64.3503) to (51.1322, 69.4324)
  arc A34 centre (-194.035, 10) radius 5 clockwise from (-194.035, 5) to (-199.035, 10)
  arc A35 centre (135.965, 10) radius 5 clockwise from (140.965, 10) to (135.965, 5)
  arc A36 centre (135.965, 75) radius 5 clockwise from (135.965, 80) to (140.965, 75)
  arc A37 centre (-194.035, 75) radius 5 clockwise from (-199.035, 75) to (-194.035, 80)
  point P95 (-199.035, 42.5)
  point P96 (140.965, 42.5)
  point P97 (-29.035, 5)
  point P98 (-29.035, 80)
  point P103 (-29.035, 42.5)
  point P105 (-72.6746, 53.9909)
  midpoint L12 P95
  midpoint L10 P96
  midpoint L9 P97
  midpoint L11 P98
  horizontal L15
  perpendicular L15 L16
  parallel L15 L17
  parallel L16 L18
  coincident L19 P103
  coincident L20 P103
  midpoint L14 P103
  horizontal L21
  vertical L22
  horizontal L23
  vertical L24
  coincident L15 P105
  dimension "d180" = 2
extrude "Extrude11" cut sketch "Sketch17" profile of C1 C2 to an object
extrude "Extrude12" cut sketch "Sketch17" profile of A1 A2 A3 A4 A5 A6 A7 A8 C1 A9 L1 A10 L2 A11 L3 A12 L4 A13 L5 A14 L6 A15 L7 A16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 against normal blind 7
work_plane "WorkPlane12"
mirror "Mirror1" mirrorStitchTolerance 0.1
extrude "Extrude13" cut sketch "Sketch17" profile of L15 L17 L18 L21 L22 L23 L24 against normal blind 30
extrude "Extrude2" cut sketch "Sketch17" profile of L15 L16 L17 L22 against normal blind 6.5
sketch "Sketch19" plane through (0, -18, 0) normal (0, -1, 0) x axis (1, 0, 0)
  line L1 (340, 80) -> (10, 80)
  line L2 (345, 10) -> (345, 75)
  line L3 (10, 5) -> (340, 5)
  line L4 (5, 75) -> (5, 10)
  line L5 (0, 10) -> (0, 75)
  line L6 (340, 0) -> (10, 0)
  line L7 (350, 75) -> (350, 10)
  line L8 (10, 85) -> (340, 85)
  line L9 (10, 80) -> (340, 80)
  line L10 (5, 10) -> (5, 75)
  line L11 (340, 5) -> (10, 5)
  line L12 (345, 75) -> (345, 10)
  line L13 (122.4221, 53.9909) -> (218.6396, 53.9909)
  line L14 (122.4221, 31.0091) -> (122.4221, 53.9909)
  line L15 (218.6396, 31.0091) -> (122.4221, 31.0091)
  line L16 (218.6396, 53.9909) -> (218.6396, 31.0091)
  line L17 (122.4221, 31.0091) -> (227.5779, 31.0091)
  line L18 (122.4221, 53.9909) -> (122.4221, 31.0091)
  line L19 (227.5779, 53.9909) -> (122.4221, 53.9909)
  line L20 (227.5779, 31.0091) -> (227.5779, 53.9909)
  arc A1 centre (340, 75) radius 5 clockwise from (340, 80) to (345, 75)
  arc A2 centre (340, 10) radius 5 clockwise from (345, 10) to (340, 5)
  arc A3 centre (10, 10) radius 5 clockwise from (10, 5) to (5, 10)
  arc A4 centre (10, 75) radius 5 clockwise from (5, 75) to (10, 80)
  arc A5 centre (10, 75) radius 10 clockwise from (0, 75) to (10, 85)
  arc A6 centre (10, 10) radius 10 clockwise from (10, 0) to (0, 10)
  arc A7 centre (340, 10) radius 10 clockwise from (350, 10) to (340, 0)
  arc A8 centre (340, 75) radius 10 clockwise from (340, 85) to (350, 75)
  arc A9 centre (340, 75) radius 5 clockwise from (340, 80) to (345, 75)
  arc A10 centre (10, 75) radius 5 clockwise from (5, 75) to (10, 80)
  arc A11 centre (10, 10) radius 5 clockwise from (10, 5) to (5, 10)
  arc A12 centre (340, 10) radius 5 clockwise from (345, 10) to (340, 5)
  circle C1 centre (72.9825, 42.5) radius 25.7849
  arc A13 centre (93.9763, 21.5062) radius 6 clockwise from (99.9148, 20.6497) to (94.8328, 15.5676)
  arc A14 centre (-51.58, 42.5) radius 153.0625 clockwise from (99.9148, 64.3503) to (99.9148, 20.6497)
  arc A15 centre (93.9763, 63.4938) radius 6 clockwise from (94.8328, 69.4324) to (99.9148, 64.3503)
  arc A16 centre (72.9825, -82.0625) radius 153.0625 clockwise from (51.1322, 69.4324) to (94.8328, 69.4324)
  arc A17 centre (51.9887, 63.4938) radius 6 clockwise from (46.0501, 64.3503) to (51.1322, 69.4324)
  arc A18 centre (197.545, 42.5) radius 153.0625 clockwise from (46.0501, 20.6497) to (46.0501, 64.3503)
  arc A19 centre (51.9887, 21.5062) radius 6 clockwise from (51.1322, 15.5676) to (46.0501, 20.6497)
  arc A20 centre (72.9825, 167.0625) radius 153.0625 clockwise from (94.8328, 15.5676) to (51.1322, 15.5676)
  circle C2 centre (277.0175, 42.5) radius 25.7849
  arc A21 centre (256.0237, 21.5062) radius 6 clockwise from (255.1672, 15.5676) to (250.0852, 20.6497)
  arc A22 centre (277.0175, 167.0625) radius 153.0625 clockwise from (298.8678, 15.5676) to (255.1672, 15.5676)
  arc A23 centre (298.0113, 21.5062) radius 6 clockwise from (303.9499, 20.6497) to (298.8678, 15.5676)
  arc A24 centre (152.455, 42.5) radius 153.0625 clockwise from (303.9499, 64.3503) to (303.9499, 20.6497)
  arc A25 centre (298.0113, 63.4938) radius 6 clockwise from (298.8678, 69.4324) to (303.9499, 64.3503)
  arc A26 centre (277.0175, -82.0625) radius 153.0625 clockwise from (255.1672, 69.4324) to (298.8678, 69.4324)
  arc A27 centre (256.0237, 63.4938) radius 6 clockwise from (250.0852, 64.3503) to (255.1672, 69.4324)
  arc A28 centre (401.58, 42.5) radius 153.0625 clockwise from (250.0852, 20.6497) to (250.0852, 64.3503)
  arc A29 centre (-51.58, 42.5) radius 153.0625 clockwise from (99.9148, 64.3503) to (99.9148, 20.6497)
  arc A30 centre (93.9763, 21.5062) radius 6 clockwise from (99.9148, 20.6497) to (94.8328, 15.5676)
  arc A31 centre (72.9825, 167.0625) radius 153.0625 clockwise from (94.8328, 15.5676) to (51.1322, 15.5676)
  arc A32 centre (51.9887, 21.5062) radius 6 clockwise from (51.1322, 15.5676) to (46.0501, 20.6497)
  arc A33 centre (197.545, 42.5) radius 153.0625 clockwise from (46.0501, 20.6497) to (46.0501, 64.3503)
  arc A34 centre (51.9887, 63.4938) radius 6 clockwise from (46.0501, 64.3503) to (51.1322, 69.4324)
  arc A35 centre (72.9825, -82.0625) radius 153.0625 clockwise from (51.1322, 69.4324) to (94.8328, 69.4324)
  arc A36 centre (93.9763, 63.4938) radius 6 clockwise from (94.8328, 69.4324) to (99.9148, 64.3503)
  arc A37 centre (401.58, 42.5) radius 153.0625 clockwise from (250.0852, 20.6497) to (250.0852, 64.3503)
  arc A38 centre (256.0237, 63.4938) radius 6 clockwise from (250.0852, 64.3503) to (255.1672, 69.4324)
  arc A39 centre (277.0175, -82.0625) radius 153.0625 clockwise from (255.1672, 69.4324) to (298.8678, 69.4324)
  arc A40 centre (298.0113, 63.4938) radius 6 clockwise from (298.8678, 69.4324) to (303.9499, 64.3503)
  arc A41 centre (152.455, 42.5) radius 153.0625 clockwise from (303.9499, 64.3503) to (303.9499, 20.6497)
  arc A42 centre (298.0113, 21.5062) radius 6 clockwise from (303.9499, 20.6497) to (298.8678, 15.5676)
  arc A43 centre (277.0175, 167.0625) radius 153.0625 clockwise from (298.8678, 15.5676) to (255.1672, 15.5676)
  arc A44 centre (256.0237, 21.5062) radius 6 clockwise from (255.1672, 15.5676) to (250.0852, 20.6497)
component_from_bodies "Body->Comp1"
position "Position12"
sketch "Sketch20" plane through (0, 0, 85) normal (0, 0, 1) x axis (-1, 0, 0)
  line L1 (-19.0012, 0) -> (-10, 0)
  line L2 (-19.0012, -252) -> (-19.0012, 0)
  line L3 (-10, -252) -> (-19.0012, -252)
  line L4 (-10, 0) -> (-10, -252)
  line L5 (-19.0012, -252) -> (-328.0012, -252)
  line L6 (-328.0012, -12) -> (-19.0012, -12)
  line L7 (-19.0012, -12) -> (-19.0012, -252)
  line L8 (-328.0012, -252) -> (-328.0012, -12)
  line L9 (-321.4377, -237.3537) -> (-321.4377, -27.1642)
  line L10 (-199.4377, -26.7527) -> (-199.4377, -237.1691)
  line L11 (-311.4791, -17.1642) -> (-209.4593, -17.1642)
  line L12 (-209.1215, -247.1642) -> (-311.4489, -247.1642)
  line L13 (-206.5084, -27.1642) -> (-314.9814, -27.1642)
  line L14 (-314.9814, -235.6377) -> (-206.5084, -235.6377)
  line L15 (-314.9814, -27.1642) -> (-314.9814, -235.6377)
  line L16 (-206.5084, -235.6377) -> (-206.5084, -27.1642)
  circle C1 centre (-112.3445, -137.7858) radius 3.4635
  circle C2 centre (-40.3445, -137.7858) radius 3.4635
  circle C3 centre (-64.3445, -137.7858) radius 3.4635
  circle C4 centre (-88.3445, -137.7858) radius 3.4679
  circle C5 centre (-37.3145, -167.3358) radius 1.55
  circle C6 centre (-121.5245, -167.3358) radius 1.55
  circle C7 centre (-37.3145, -195.4358) radius 1.55
  circle C8 centre (-121.5245, -195.4358) radius 1.55
  arc A1 centre (-209.4293, -27.1642) radius 10 clockwise from (-209.4593, -17.1642) to (-199.4377, -26.7527)
  arc A2 centre (-311.4377, -27.1642) radius 10 clockwise from (-321.4377, -27.1642) to (-311.4791, -17.1642)
  arc A3 centre (-209.4377, -237.1692) radius 10 clockwise from (-199.4377, -237.1691) to (-209.1215, -247.1642)
  arc A4 centre (-311.4395, -237.1642) radius 10 clockwise from (-311.4489, -247.1642) to (-321.4377, -237.3537)
  circle C9 centre (-107.2693, -126.6125) radius 54
  circle C10 centre (-107.2693, -126.6125) radius 85
  point P4 (-19.0012, -252)
  point P35 (-19.0012, -252)
  point P6 (-19.0012, -12)
  point P8 (-328.0012, -12)
  point P7 (-328.0012, -252)
  point P34 (-107.2693, -126.6125)
  vertical L7
  horizontal L5
  horizontal L6
  vertical L8
  concentric C9 C10
  coincident P4 P35
  dimension "d189" distance P6 P8 = 309
  dimension "d190" distance P7 P8 = 240
  dimension "d191" diameter C9 = 108
  dimension "d192" diameter C10 = 170
  dimension "d193" distance L6 P34 = 114.6125
  dimension "d194" distance L7 P34 = 88.2681
  dimension "d195" distance L6 L11 = 5.1642
  dimension "d196" distance L8 L9 = 6.5635
  dimension "d197" distance L5 L12 = 4.8358
  dimension "d198" distance L12 L14 = 11.5265
  dimension "d199" distance L11 L13 = 10
  dimension "d200" distance L9 L15 = 6.4563
  dimension "d201" distance L15 L16 = 108.473
  dimension "d202" distance L8 L10 = 128.5635
position "Position13"
sketch "Sketch21" plane through (0, 0, 12) normal (0, 0, 1) x axis (-1, 0, 0)
  line L1 (-333, 0) -> (-17, 0)
  line L2 (-333, -252) -> (-333, 0)
  line L3 (-17, -252) -> (-333, -252)
  line L4 (-17, 0) -> (-17, -252)
  line L5 (-147.1419, -154.2057) -> (-118.8355, -154.2057)
  line L6 (-147.1419, -144.4057) -> (-147.1419, -154.2057)
  line L7 (-131.2706, -144.4057) -> (-147.1419, -144.4057)
  curve K1 (-116.0627, -97.9357) -> (-112.1419, -91.5786)
  curve K2 (-98.221, -97.9357) -> (-102.1419, -91.5786)
  curve K3 (-78.4989, -117.6578) -> (-72.1419, -121.5786)
  curve K4 (-78.4989, -135.4995) -> (-72.1419, -131.5786)
  line L8 (-95.8894, -148.5786) -> (-95.8894, -154.3883)
  line L9 (-118.7304, -148.5786) -> (-95.8894, -148.5786)
  line L10 (-118.7304, -154.25) -> (-118.7304, -148.5786)
  line L11 (-189.6419, -144.4057) -> (-189.6419, -104.4057)
  line L12 (-203.437, -144.4057) -> (-189.6419, -144.4057)
  line L13 (-203.437, -104.4057) -> (-203.437, -144.4057)
  line L14 (-189.6419, -104.4057) -> (-203.437, -104.4057)
  circle C1 centre (-25.0012, -108) radius 2
  circle C2 centre (-324.9988, -27) radius 3.4926
  circle C3 centre (-25.0012, -188.5138) radius 2.9725
  circle C4 centre (-324.9988, -108) radius 2
  circle C5 centre (-324.9988, -189) radius 2
  circle C6 centre (-25.0012, -27.4042) radius 3.2246
  circle C7 centre (-72.1419, -126.5786) radius 2
  circle C8 centre (-107.1419, -91.5786) radius 2
  circle C9 centre (-107.1419, -113.007) radius 2.7
  circle C10 centre (-118.8952, -133.3644) radius 2.7
  circle C11 centre (-95.3886, -133.3644) radius 2.7
  arc A1 centre (-107.1419, -126.5786) radius 30 clockwise from (-131.2706, -144.4057) to (-116.0627, -97.9357)
  arc A2 centre (-107.1419, -91.5786) radius 5 clockwise from (-112.1419, -91.5786) to (-102.1419, -91.5786)
  arc A3 centre (-107.1419, -126.5786) radius 30 clockwise from (-98.221, -97.9357) to (-78.4989, -117.6578)
  arc A4 centre (-72.1419, -126.5786) radius 5 clockwise from (-72.1419, -121.5786) to (-72.1419, -131.5786)
  arc A5 centre (-107.1419, -126.5786) radius 30 clockwise from (-78.4989, -135.4995) to (-95.8894, -154.3883)
  arc A6 centre (-107.1419, -126.5786) radius 30 clockwise from (-118.7304, -154.25) to (-118.8355, -154.2057)
  circle C12 centre (-197.7894, -124.4057) radius 2.1
component_insert "Component Insert9"
sketch "top mill" plane through (0, 0, 0) normal (0, 0, 1) x axis (1, 0, 0)
  line L1 (330.0012, 239) -> (19.0012, 239)
  line L2 (330.0012, 0) -> (330.0012, 239)
  line L3 (19.0012, 0) -> (330.0012, 0)
  line L4 (19.0012, 239) -> (19.0012, 0)
  line L5 (31.5012, 239) -> (19.0012, 239)
  line L6 (31.5012, 0) -> (31.5012, 239)
  line L7 (19.0012, 0) -> (31.5012, 0)
  line L8 (19.0012, 239) -> (19.0012, 0)
  line L9 (317.5012, 239) -> (330.0012, 239)
  line L10 (317.5012, 0) -> (317.5012, 239)
  line L11 (330.0012, 0) -> (317.5012, 0)
  line L12 (330.0012, 239) -> (330.0012, 0)
  line L13 (174.5012, 0) -> (174.5012, 239)
  line L14 (19.0012, 252) -> (19.0012, 0)
  line L15 (330.9988, 252) -> (330.9988, 0)
  line L16 (314.9814, 14.6642) -> (314.9814, 223.1377)
  line L17 (206.5084, 14.6642) -> (314.9814, 14.6642)
  line L18 (206.5084, 223.1377) -> (206.5084, 14.6642)
  line L19 (314.9814, 223.1377) -> (206.5084, 223.1377)
  line L20 (311.4791, 4.6642) -> (209.4593, 4.6642)
  line L21 (321.4377, 224.8537) -> (321.4377, 14.6642)
  line L22 (209.1215, 234.6642) -> (311.4489, 234.6642)
  line L23 (199.4377, 14.2527) -> (199.4377, 224.6691)
  circle C1 centre (107.1419, 126.5786) radius 54
  arc A1 centre (311.4377, 14.6642) radius 10 clockwise from (321.4377, 14.6642) to (311.4791, 4.6642)
  arc A2 centre (311.4395, 224.6642) radius 10 clockwise from (311.4489, 234.6642) to (321.4377, 224.8537)
  arc A3 centre (209.4377, 224.6692) radius 10 clockwise from (199.4377, 224.6691) to (209.1215, 234.6642)
  arc A4 centre (209.4293, 14.6642) radius 10 clockwise from (209.4593, 4.6642) to (199.4377, 14.2527)
  point P7 (31.5012, 0)
  point P10 (317.5012, 0)
  point P12 (174.5012, 239)
  point P13 (174.5012, 0)
  point P5 (19.0012, 0)
  point P18 (19.0012, 0)
  point P2 (19.0012, 239)
  point P3 (330.0012, 239)
  point P19 (107.1419, 126.5786)
  horizontal L1
  vertical L2
  horizontal L3
  vertical L4
  horizontal L5
  vertical L6
  horizontal L7
  vertical L8
  coincident L3 P7
  horizontal L9
  vertical L10
  horizontal L11
  vertical L12
  coincident L3 P10
  midpoint L1 P12
  midpoint L3 P13
  coincident P5 P18
  dimension "d203" distance P2 P3 = 311
  dimension "d204" distance P2 P5 = 239
  dimension "d205" distance L6 L10 = 286
  dimension "d206" distance L6 L8 = 12.5 (= "( ( 311 - 286 ) / 2 ) * 1 mm")
  dimension "d207" diameter C1 = 108
  dimension "d208" distance L3 P19 = 126.5786
  dimension "d209" distance L6 P19 = 75.6407
  dimension "d210" distance L1 L22 = 4.3358
  dimension "d211" distance L3 L20 = 4.6642
position "Position14"
sketch "Sketch24" plane through (225.3877, 0, 0) normal (-1, 0, 0) x axis (0, -1, 0)
  line L1 (-143.2359, 13.9004) -> (-209.1659, 13.9004)
  line L2 (-143.2359, 56.4304) -> (-143.2359, 13.9004)
  line L3 (-209.1659, 56.4304) -> (-143.2359, 56.4304)
  line L4 (-209.1659, 13.9004) -> (-209.1659, 56.4304)
  line L5 (-199.5112, 38.5202) -> (-209.1659, 38.5202)
  line L6 (-199.5112, 13.9004) -> (-199.5112, 38.5202)
  line L7 (-209.1659, 13.9004) -> (-199.5112, 13.9004)
  line L8 (-209.1659, 38.5202) -> (-209.1659, 13.9004)
  line L9 (-143.2359, 19.9004) -> (-209.1659, 19.9004)
  line L10 (-143.2359, 10.9004) -> (-143.2359, 19.9004)
  line L11 (-209.1659, 10.9004) -> (-143.2359, 10.9004)
  line L12 (-209.1659, 19.9004) -> (-209.1659, 10.9004)
  line L13 (-151.6314, 10.9004) -> (-143.2359, 10.9004)
  line L14 (-151.6314, 32.9004) -> (-151.6314, 10.9004)
  line L15 (-143.2359, 32.9004) -> (-151.6314, 32.9004)
  line L16 (-143.2359, 10.9004) -> (-143.2359, 32.9004)
  circle C1 centre (-145.9759, 16.4754) radius 1.55
  circle C2 centre (-205.4559, 16.4754) radius 1.55
  circle C3 centre (-206.0159, 33.3454) radius 1.55
  point P11 (-199.5112, 13.9004)
  point P9 (-209.1659, 38.5202)
  point P13 (-209.1659, 19.9004)
  point P15 (-143.2359, 10.9004)
  point P19 (-143.2359, 32.9004)
  horizontal L5
  vertical L6
  horizontal L7
  vertical L8
  coincident L1 P11
  coincident L4 P9
  horizontal L9
  vertical L10
  horizontal L11
  vertical L12
  coincident L8 P13
  horizontal L13
  vertical L14
  horizontal L15
  vertical L16
  dimension "d212" distance L1 L11 = 3
  dimension "d213" distance L9 L11 = 9
  dimension "d229" distance P15 P19 = 22
extrude "Extrude3" new body sketch "Sketch24" profile of L1 L2 L4 C1 C2 C3 L5 L6 L7 L8 L9 L10 L11 L12 L13 L14 L15 L16 along normal blind 2
sketch "Sketch25" plane through (226.8977, 0, 0) normal (1, 0, 0) x axis (0, 1, 0)
  line L1 (209.1659, 13.9004) -> (143.2359, 13.9004)
  line L2 (209.1659, 56.4304) -> (209.1659, 13.9004)
  line L3 (143.2359, 56.4304) -> (209.1659, 56.4304)
  line L4 (143.2359, 13.9004) -> (143.2359, 56.4304)
  line L5 (149, 21.3218) -> (143.2359, 21.3218)
  line L6 (149, 11) -> (149, 21.3218)
  line L7 (143.2359, 11) -> (149, 11)
  line L8 (143.2359, 21.3218) -> (143.2359, 11)
  line L9 (209.2, 13.9004) -> (143.2359, 13.9004)
  line L10 (209.2, 10.9) -> (209.2, 13.9004)
  line L11 (143.2359, 10.9) -> (209.2, 10.9)
  line L12 (143.2359, 13.9004) -> (143.2359, 10.9)
  line L13 (209.1659, 18.6647) -> (201.4002, 18.6647)
  line L14 (209.1659, 13.9004) -> (209.1659, 18.6647)
  line L15 (201.4002, 13.9004) -> (209.1659, 13.9004)
  line L16 (201.4002, 18.6647) -> (201.4002, 13.9004)
  circle C1 centre (145.9759, 16.4754) radius 1.55
  circle C2 centre (205.4559, 16.4754) radius 1.55
  circle C3 centre (206.0159, 33.3454) radius 1.55
  circle C4 centre (205.4559, 16.4754) radius 1.55
  circle C5 centre (145.9759, 16.4754) radius 1.55
  point P9 (143.2359, 21.3218)
  point P2 (143.2359, 13.9004)
  point P13 (143.2359, 13.9004)
  point P3 (209.1659, 13.9004)
  point P19 (209.1659, 13.9004)
  horizontal L5
  vertical L6
  horizontal L7
  vertical L8
  coincident L4 P9
  horizontal L9
  vertical L10
  horizontal L11
  vertical L12
  coincident P2 P13
  horizontal L13
  vertical L14
  horizontal L15
  vertical L16
  coincident P3 P19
